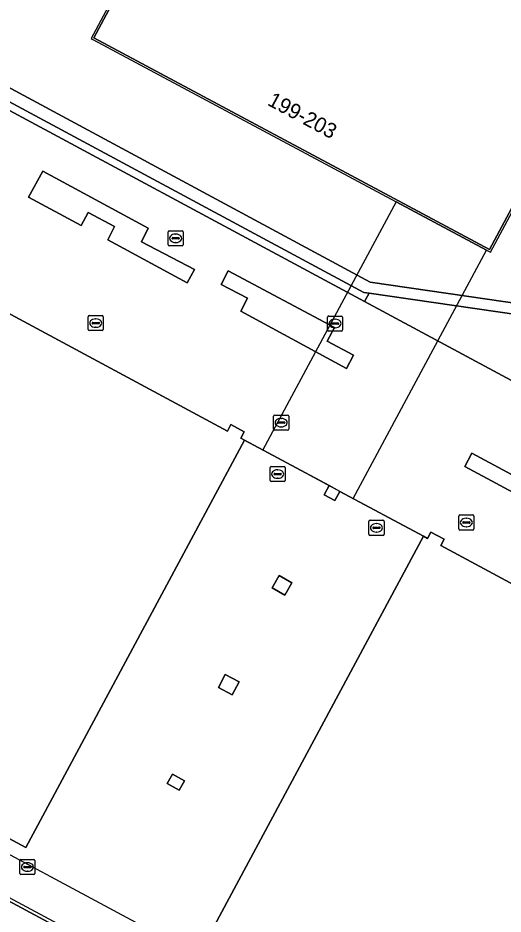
# Model space of a CAD drawing. Extents: x 159489 to 160304, y 383825 to 384531.
# Drawn here: x 159703.5 to 159735.7, y 384277.9 to 384337.5 of the extents above; entities that cross this region are included whole.
import ezdxf

# ---------------------------------------------------------------- set-up
doc = ezdxf.new("R2010")
doc.units = 0
for name, color, linetype in [('IMGEO_Dek', 7, 'Continuous'), ('IMGEO_Groenvoorziening', 7, 'Continuous'), ('IMGEO_Kolk', 7, 'Continuous'), ('IMGEO_Lijnafwatering', 7, 'Continuous'), ('IMGEO_Pand', 7, 'Continuous'), ('IMGEO_Pand_nummerreeks', 7, 'Continuous'), ('IMGEO_Pand_overbouw', 7, 'Continuous'), ('IMGEO_Rioolput', 7, 'Continuous'), ('IMGEO_Terreindeel_open', 7, 'Continuous'), ('IMGEO_Voetpad_gesloten', 7, 'Continuous'), ('IMGEO_Voetpad_open', 7, 'Continuous')]:
    doc.layers.add(name, color=color, linetype=linetype)

msp = doc.modelspace()

# ---------------------------------------------------------------- linework, layer by layer
at = {"layer": 'IMGEO_Dek'}
msp.add_lwpolyline([(159734.596, 384322.101), (159728.589, 384325.319), (159719.719, 384308.817), (159725.721, 384305.59)], close=True, dxfattribs=at)
at = {"layer": 'IMGEO_Groenvoorziening'}
for points in [[(159705.101, 384327.367), (159704.159, 384325.622), (159707.658, 384323.74), (159708.13, 384324.61), (159709.88, 384323.672), (159709.423, 384322.784), (159714.71, 384319.933), (159715.178, 384320.807), (159711.668, 384322.666), (159712.108, 384323.561)], [(159724.481, 384316.952), (159717.417, 384320.724), (159716.952, 384319.819), (159718.713, 384318.921), (159718.256, 384318.05), (159725.298, 384314.239), (159725.754, 384315.114), (159724.004, 384316.059)], [(159733.627, 384308.609), (159733.153, 384307.722), (159741.96, 384302.978), (159742.427, 384303.848)]]:
    msp.add_lwpolyline(points, close=True, dxfattribs=at)
at = {"layer": 'IMGEO_Kolk'}
for p, q in [((159713.436, 384322.465), (159713.436, 384323.317)), ((159713.511, 384323.391), (159714.363, 384323.391)), ((159713.738, 384322.934), (159714.136, 384322.934)), ((159713.924, 384323.171), (159713.949, 384323.171)), ((159714.437, 384323.317), (159714.437, 384322.465)), ((159714.363, 384322.391), (159713.511, 384322.391)), ((159713.695, 384322.885), (159713.695, 384322.897)), ((159714.133, 384322.848), (159713.735, 384322.848)), ((159713.947, 384322.611), (159713.922, 384322.611)), ((159714.179, 384322.897), (159714.179, 384322.885)), ((159708.125, 384316.825), (159708.125, 384317.677)), ((159708.2, 384317.751), (159709.052, 384317.751)), ((159709.126, 384317.677), (159709.126, 384316.825)), ((159724.028, 384316.798), (159724.028, 384317.65)), ((159724.103, 384317.724), (159724.955, 384317.724)), ((159725.029, 384317.65), (159725.029, 384316.798)), ((159708.384, 384317.245), (159708.384, 384317.257)), ((159708.822, 384317.208), (159708.424, 384317.208)), ((159708.427, 384317.294), (159708.825, 384317.294)), ((159708.636, 384316.971), (159708.611, 384316.971)), ((159708.613, 384317.531), (159708.638, 384317.531)), ((159708.868, 384317.257), (159708.868, 384317.245)), ((159724.287, 384317.218), (159724.287, 384317.23)), ((159724.725, 384317.181), (159724.327, 384317.181)), ((159724.33, 384317.267), (159724.728, 384317.267)), ((159724.516, 384317.504), (159724.541, 384317.504)), ((159724.771, 384317.23), (159724.771, 384317.218)), ((159709.052, 384316.751), (159708.2, 384316.751)), ((159724.955, 384316.724), (159724.103, 384316.724)), ((159724.539, 384316.944), (159724.514, 384316.944)), ((159720.445, 384310.206), (159720.445, 384311.058)), ((159720.52, 384311.132), (159721.372, 384311.132)), ((159721.446, 384311.058), (159721.446, 384310.206)), ((159720.704, 384310.626), (159720.704, 384310.638)), ((159721.142, 384310.589), (159720.744, 384310.589)), ((159720.747, 384310.675), (159721.145, 384310.675)), ((159720.933, 384310.912), (159720.958, 384310.912)), ((159721.188, 384310.638), (159721.188, 384310.626)), ((159721.372, 384310.132), (159720.52, 384310.132)), ((159720.956, 384310.352), (159720.931, 384310.352)), ((159720.214, 384306.786), (159720.214, 384307.638)), ((159720.289, 384307.712), (159721.141, 384307.712)), ((159720.702, 384307.492), (159720.727, 384307.492)), ((159721.215, 384307.638), (159721.215, 384306.786)), ((159720.473, 384307.206), (159720.473, 384307.218)), ((159720.911, 384307.169), (159720.513, 384307.169)), ((159720.516, 384307.255), (159720.914, 384307.255)), ((159720.725, 384306.932), (159720.7, 384306.932)), ((159720.957, 384307.218), (159720.957, 384307.206)), ((159721.141, 384306.712), (159720.289, 384306.712)), ((159732.827, 384304.491), (159733.679, 384304.491)), ((159726.779, 384303.211), (159726.779, 384304.063)), ((159726.854, 384304.137), (159727.706, 384304.137)), ((159727.267, 384303.917), (159727.292, 384303.917)), ((159727.78, 384304.063), (159727.78, 384303.211)), ((159732.752, 384303.565), (159732.752, 384304.417)), ((159733.011, 384303.985), (159733.011, 384303.997)), ((159733.449, 384303.948), (159733.051, 384303.948)), ((159733.054, 384304.034), (159733.452, 384304.034)), ((159733.24, 384304.271), (159733.265, 384304.271)), ((159733.495, 384303.997), (159733.495, 384303.985)), ((159733.753, 384304.417), (159733.753, 384303.565)), ((159727.038, 384303.631), (159727.038, 384303.643)), ((159727.476, 384303.594), (159727.078, 384303.594)), ((159727.081, 384303.68), (159727.479, 384303.68)), ((159727.29, 384303.357), (159727.265, 384303.357)), ((159727.522, 384303.643), (159727.522, 384303.631)), ((159733.679, 384303.491), (159732.827, 384303.491)), ((159733.263, 384303.711), (159733.238, 384303.711)), ((159727.706, 384303.137), (159726.854, 384303.137))]:
    msp.add_line(p, q, dxfattribs=at)
for points in [[(159713.436, 384322.465), (159713.436, 384323.317)], [(159713.511, 384323.391), (159714.363, 384323.391)], [(159714.437, 384323.317), (159714.437, 384322.465)], [(159714.363, 384322.391), (159713.511, 384322.391)], [(159708.125, 384316.825), (159708.125, 384317.677)], [(159708.2, 384317.751), (159709.052, 384317.751)], [(159709.126, 384317.677), (159709.126, 384316.825)], [(159724.028, 384316.798), (159724.028, 384317.65)], [(159724.103, 384317.724), (159724.955, 384317.724)], [(159725.029, 384317.65), (159725.029, 384316.798)], [(159709.052, 384316.751), (159708.2, 384316.751)], [(159724.955, 384316.724), (159724.103, 384316.724)], [(159720.445, 384310.206), (159720.445, 384311.058)], [(159720.52, 384311.132), (159721.372, 384311.132)], [(159721.446, 384311.058), (159721.446, 384310.206)], [(159721.372, 384310.132), (159720.52, 384310.132)], [(159720.214, 384306.786), (159720.214, 384307.638)], [(159720.289, 384307.712), (159721.141, 384307.712)], [(159721.215, 384307.638), (159721.215, 384306.786)], [(159721.141, 384306.712), (159720.289, 384306.712)], [(159732.827, 384304.491), (159733.679, 384304.491)], [(159726.779, 384303.211), (159726.779, 384304.063)], [(159726.854, 384304.137), (159727.706, 384304.137)], [(159727.78, 384304.063), (159727.78, 384303.211)], [(159732.752, 384303.565), (159732.752, 384304.417)], [(159733.753, 384304.417), (159733.753, 384303.565)], [(159733.679, 384303.491), (159732.827, 384303.491)], [(159727.706, 384303.137), (159726.854, 384303.137)]]:
    msp.add_lwpolyline(points, dxfattribs=at)
for centre, radius, start, end in [((159713.513, 384323.315), 0.0765, 91.55205, 178.44795), ((159713.513, 384323.315), 0.0765, 91.55205, 178.44795), ((159713.735, 384322.894), 0.0403, 85.87752, 175.75265), ((159714.14, 384322.896), 0.0386, 1.73085, 96.63898), ((159714.361, 384323.315), 0.0765, 1.55205, 88.44795), ((159714.361, 384323.315), 0.0765, 1.55205, 88.44795), ((159713.513, 384322.467), 0.0765, 181.55205, 268.44795), ((159713.513, 384322.467), 0.0765, 181.55205, 268.44795), ((159713.732, 384322.884), 0.0366, 178.93798, 274.71019), ((159714.136, 384322.891), 0.043, 264.86636, 352.45326), ((159714.361, 384322.467), 0.0765, 271.55205, 358.44795), ((159714.361, 384322.467), 0.0765, 271.55205, 358.44795), ((159708.202, 384317.675), 0.0765, 91.55205, 178.44795), ((159708.202, 384317.675), 0.0765, 91.55205, 178.44795), ((159709.05, 384317.675), 0.0765, 1.55205, 88.44795), ((159709.05, 384317.675), 0.0765, 1.55205, 88.44795), ((159724.105, 384317.648), 0.0765, 91.55205, 178.44795), ((159724.105, 384317.648), 0.0765, 91.55205, 178.44795), ((159724.953, 384317.648), 0.0765, 1.55205, 88.44795), ((159724.953, 384317.648), 0.0765, 1.55205, 88.44795), ((159708.424, 384317.254), 0.0403, 85.87752, 175.75265), ((159708.421, 384317.244), 0.0366, 178.93798, 274.71019), ((159708.825, 384317.251), 0.043, 264.86636, 352.45326), ((159708.829, 384317.256), 0.0386, 1.73085, 96.63898), ((159724.327, 384317.227), 0.0403, 85.87752, 175.75265), ((159724.324, 384317.217), 0.0366, 178.93798, 274.71019), ((159724.728, 384317.224), 0.043, 264.86636, 352.45326), ((159724.732, 384317.229), 0.0386, 1.73085, 96.63898), ((159708.202, 384316.827), 0.0765, 181.55205, 268.44795), ((159708.202, 384316.827), 0.0765, 181.55205, 268.44795), ((159709.05, 384316.827), 0.0765, 271.55205, 358.44795), ((159709.05, 384316.827), 0.0765, 271.55205, 358.44795), ((159724.105, 384316.8), 0.0765, 181.55205, 268.44795), ((159724.105, 384316.8), 0.0765, 181.55205, 268.44795), ((159724.953, 384316.8), 0.0765, 271.55205, 358.44795), ((159724.953, 384316.8), 0.0765, 271.55205, 358.44795), ((159720.522, 384311.056), 0.0765, 91.55205, 178.44795), ((159720.522, 384311.056), 0.0765, 91.55205, 178.44795), ((159721.37, 384311.056), 0.0765, 1.55205, 88.44795), ((159721.37, 384311.056), 0.0765, 1.55205, 88.44795), ((159720.744, 384310.635), 0.0403, 85.87752, 175.75265), ((159720.741, 384310.625), 0.0366, 178.93798, 274.71019), ((159721.145, 384310.632), 0.043, 264.86636, 352.45326), ((159721.149, 384310.637), 0.0386, 1.73085, 96.63898), ((159720.522, 384310.208), 0.0765, 181.55205, 268.44795), ((159720.522, 384310.208), 0.0765, 181.55205, 268.44795), ((159721.37, 384310.208), 0.0765, 271.55205, 358.44795), ((159721.37, 384310.208), 0.0765, 271.55205, 358.44795), ((159720.291, 384307.636), 0.0765, 91.55205, 178.44795), ((159720.291, 384307.636), 0.0765, 91.55205, 178.44795), ((159721.139, 384307.636), 0.0765, 1.55205, 88.44795), ((159721.139, 384307.636), 0.0765, 1.55205, 88.44795), ((159720.513, 384307.215), 0.0403, 85.87752, 175.75265), ((159720.51, 384307.205), 0.0366, 178.93798, 274.71019), ((159720.914, 384307.212), 0.043, 264.86636, 352.45326), ((159720.918, 384307.217), 0.0386, 1.73085, 96.63898), ((159720.291, 384306.788), 0.0765, 181.55205, 268.44795), ((159720.291, 384306.788), 0.0765, 181.55205, 268.44795), ((159721.139, 384306.788), 0.0765, 271.55205, 358.44795), ((159721.139, 384306.788), 0.0765, 271.55205, 358.44795), ((159732.829, 384304.415), 0.0765, 91.55205, 178.44795), ((159732.829, 384304.415), 0.0765, 91.55205, 178.44795), ((159733.677, 384304.415), 0.0765, 1.55205, 88.44795), ((159733.677, 384304.415), 0.0765, 1.55205, 88.44795), ((159726.856, 384304.061), 0.0765, 91.55205, 178.44795), ((159726.856, 384304.061), 0.0765, 91.55205, 178.44795), ((159727.704, 384304.061), 0.0765, 1.55205, 88.44795), ((159727.704, 384304.061), 0.0765, 1.55205, 88.44795), ((159733.051, 384303.994), 0.0403, 85.87752, 175.75265), ((159733.048, 384303.984), 0.0366, 178.93798, 274.71019), ((159733.452, 384303.991), 0.043, 264.86636, 352.45326), ((159733.456, 384303.996), 0.0386, 1.73085, 96.63898), ((159727.078, 384303.64), 0.0403, 85.87752, 175.75265), ((159727.075, 384303.63), 0.0366, 178.93798, 274.71019), ((159727.479, 384303.637), 0.043, 264.86636, 352.45326), ((159727.483, 384303.642), 0.0386, 1.73085, 96.63898), ((159732.829, 384303.567), 0.0765, 181.55205, 268.44795), ((159732.829, 384303.567), 0.0765, 181.55205, 268.44795), ((159733.677, 384303.567), 0.0765, 271.55205, 358.44795), ((159733.677, 384303.567), 0.0765, 271.55205, 358.44795), ((159726.856, 384303.213), 0.0765, 181.55205, 268.44795), ((159726.856, 384303.213), 0.0765, 181.55205, 268.44795), ((159727.704, 384303.213), 0.0765, 271.55205, 358.44795), ((159727.704, 384303.213), 0.0765, 271.55205, 358.44795)]:
    msp.add_arc(centre, radius, start, end, dxfattribs=at)
for centre, major_axis, ratio, start_param, end_param in [((159713.923, 384322.891), (-0.387, 0.002), 0.722429, 4.712389, 7.853982), ((159713.948, 384322.891), (-0.39, 0.002), 0.717154, 1.570796, 4.712389), ((159708.612, 384317.251), (-0.387, 0.002), 0.722429, 4.712389, 7.853982), ((159708.637, 384317.251), (-0.39, 0.002), 0.717154, 1.570796, 4.712389), ((159724.515, 384317.224), (-0.387, 0.002), 0.722429, 4.712389, 7.853982), ((159724.54, 384317.224), (-0.39, 0.002), 0.717154, 1.570796, 4.712389), ((159720.932, 384310.632), (-0.387, 0.002), 0.722429, 4.712389, 7.853982), ((159720.957, 384310.632), (-0.39, 0.002), 0.717154, 1.570796, 4.712389), ((159720.701, 384307.212), (-0.387, 0.002), 0.722429, 4.712389, 7.853982), ((159720.726, 384307.212), (-0.39, 0.002), 0.717154, 1.570796, 4.712389), ((159727.266, 384303.637), (-0.387, 0.002), 0.722429, 4.712389, 7.853982), ((159727.291, 384303.637), (-0.39, 0.002), 0.717154, 1.570796, 4.712389), ((159733.239, 384303.991), (-0.387, 0.002), 0.722429, 4.712389, 7.853982), ((159733.264, 384303.991), (-0.39, 0.002), 0.717154, 1.570796, 4.712389)]:
    msp.add_ellipse(centre, major_axis=major_axis, ratio=ratio, start_param=start_param, end_param=end_param, dxfattribs=at)
at = {"layer": 'IMGEO_Lijnafwatering'}
msp.add_lwpolyline([(159711.214, 384274.544), (159694.446, 384283.552)], dxfattribs=at)
at = {"layer": 'IMGEO_Pand'}
for points in [[(159744.495, 384340.27), (159745.463, 384342.08), (159719.159, 384356.157), (159718.221, 384354.406), (159717.843, 384353.7), (159708.49, 384336.235), (159734.794, 384322.143), (159744.117, 384339.565)], [(159718.52, 384309.461), (159718.256, 384309.603), (159718.485, 384310.029), (159717.604, 384310.502), (159717.376, 384310.076), (159693.74, 384322.781), (159693.668, 384322.82), (159692.216, 384320.108), (159684.806, 384306.264), (159683.295, 384303.441), (159678.693, 384294.844), (159693.021, 384287.138), (159693.055, 384287.196), (159693.529, 384288.01), (159703.988, 384282.369)], [(159747.439, 384293.915), (159731.551, 384302.457), (159731.779, 384302.882), (159730.898, 384303.355), (159730.67, 384302.93), (159730.406, 384303.072), (159715.868, 384275.99), (159766.025, 384249.054), (159765.572, 384248.208), (159765.546, 384248.161), (159779.824, 384240.489), (159781.812, 384244.448), (159783.972, 384248.491), (159794.191, 384267.623), (159794.673, 384268.525)], [(159721.661, 384299.975), (159720.815, 384300.466), (159720.343, 384299.654), (159721.19, 384299.162)], [(159718.149, 384293.384), (159717.236, 384293.874), (159716.775, 384293.016), (159717.688, 384292.525)], [(159714.521, 384286.819), (159713.736, 384287.261), (159713.378, 384286.626), (159714.163, 384286.183)]]:
    msp.add_lwpolyline(points, close=True, dxfattribs=at)
at = {"layer": 'IMGEO_Pand_overbouw'}
for points in [[(159772.845, 384392.873), (159746.364, 384407.132), (159719.057, 384356.211), (159708.316, 384336.181), (159708.428, 384336.121), (159728.589, 384325.319), (159734.596, 384322.101), (159734.859, 384321.96), (159745.598, 384342.008)], [(159745.463, 384342.08), (159744.495, 384340.27), (159744.117, 384339.565), (159734.794, 384322.143), (159708.49, 384336.235), (159717.843, 384353.7), (159718.221, 384354.406), (159719.159, 384356.157)], [(159718.52, 384309.461), (159703.988, 384282.369), (159693.529, 384288.01), (159693.055, 384287.196), (159765.572, 384248.208), (159766.025, 384249.054), (159715.868, 384275.99), (159730.406, 384303.072), (159724.846, 384306.056), (159724.134, 384306.443)]]:
    msp.add_lwpolyline(points, close=True, dxfattribs=at)
at = {"layer": 'IMGEO_Rioolput'}
for p, q in [((159703.583, 384280.651), (159703.583, 384281.503)), ((159703.658, 384281.577), (159704.51, 384281.577)), ((159704.071, 384281.357), (159704.096, 384281.357)), ((159704.584, 384281.503), (159704.584, 384280.651)), ((159703.842, 384281.071), (159703.842, 384281.083)), ((159704.28, 384281.034), (159703.882, 384281.034)), ((159703.885, 384281.12), (159704.283, 384281.12)), ((159704.094, 384280.797), (159704.069, 384280.797)), ((159704.326, 384281.083), (159704.326, 384281.071)), ((159704.51, 384280.577), (159703.658, 384280.577))]:
    msp.add_line(p, q, dxfattribs=at)
for points in [[(159703.583, 384280.651), (159703.583, 384281.503)], [(159703.658, 384281.577), (159704.51, 384281.577)], [(159704.584, 384281.503), (159704.584, 384280.651)], [(159704.51, 384280.577), (159703.658, 384280.577)]]:
    msp.add_lwpolyline(points, dxfattribs=at)
for centre, radius, start, end in [((159703.66, 384281.501), 0.0765, 91.55205, 178.44795), ((159703.66, 384281.501), 0.0765, 91.55205, 178.44795), ((159704.508, 384281.501), 0.0765, 1.55205, 88.44795), ((159704.508, 384281.501), 0.0765, 1.55205, 88.44795), ((159703.66, 384280.653), 0.0765, 181.55205, 268.44795), ((159703.66, 384280.653), 0.0765, 181.55205, 268.44795), ((159703.882, 384281.08), 0.0403, 85.87752, 175.75265), ((159703.879, 384281.07), 0.0366, 178.93798, 274.71019), ((159704.283, 384281.077), 0.043, 264.86636, 352.45326), ((159704.287, 384281.082), 0.0386, 1.73085, 96.63898), ((159704.508, 384280.653), 0.0765, 271.55205, 358.44795), ((159704.508, 384280.653), 0.0765, 271.55205, 358.44795)]:
    msp.add_arc(centre, radius, start, end, dxfattribs=at)
for centre, major_axis, ratio, start_param, end_param in [((159704.07, 384281.077), (-0.387, 0.002), 0.722429, 4.712389, 7.853982), ((159704.095, 384281.077), (-0.39, 0.002), 0.717154, 1.570796, 4.712389)]:
    msp.add_ellipse(centre, major_axis=major_axis, ratio=ratio, start_param=start_param, end_param=end_param, dxfattribs=at)
at = {"layer": 'IMGEO_Terreindeel_open'}
msp.add_lwpolyline([(159797.007, 384309.896), (159741.046, 384317.91), (159726.866, 384319.977), (159700.707, 384334.064), (159712.762, 384356.443), (159717.843, 384353.7), (159718.221, 384354.406), (159712.442, 384357.532), (159699.61, 384333.72), (159726.44, 384319.286), (159726.801, 384319.234), (159741.002, 384317.183), (159741.576, 384317.086), (159796.909, 384309.117), (159800.043, 384308.652), (159800.185, 384309.411), (159801.736, 384308.601), (159802.101, 384309.308), (159781.459, 384320.418), (159744.495, 384340.27), (159744.117, 384339.565), (159781.262, 384319.609), (159800.092, 384309.462)], close=True, dxfattribs=at)
at = {"layer": 'IMGEO_Voetpad_gesloten'}
for points in [[(159744.117, 384339.565), (159734.794, 384322.143), (159708.49, 384336.235), (159717.843, 384353.7), (159712.762, 384356.443), (159700.707, 384334.064), (159726.866, 384319.977), (159741.046, 384317.91), (159797.007, 384309.896), (159800.092, 384309.462), (159781.262, 384319.609)], [(159734.596, 384322.101), (159728.589, 384325.319), (159719.719, 384308.817), (159725.721, 384305.59)]]:
    msp.add_lwpolyline(points, close=True, dxfattribs=at)
at = {"layer": 'IMGEO_Voetpad_open'}
for points in [[(159712.442, 384357.532), (159712.638, 384357.799), (159712.207, 384358.023), (159699.16, 384333.403), (159699.381, 384333.281), (159726.485, 384318.691), (159726.801, 384319.234), (159726.44, 384319.286), (159699.61, 384333.72)], [(159705.101, 384327.367), (159712.108, 384323.561), (159711.668, 384322.666), (159715.178, 384320.807), (159714.71, 384319.933), (159709.423, 384322.784), (159709.88, 384323.672), (159708.13, 384324.61), (159707.658, 384323.74), (159704.159, 384325.622)], [(159724.481, 384316.952), (159724.004, 384316.059), (159725.754, 384315.114), (159725.298, 384314.239), (159718.256, 384318.05), (159718.713, 384318.921), (159716.952, 384319.819), (159717.417, 384320.724)], [(159726.801, 384319.234), (159726.485, 384318.691), (159736.839, 384313.125), (159737.034, 384313.652), (159737.45, 384314.29), (159738.511, 384313.717), (159738.631, 384314.476), (159741.156, 384314.134), (159741.576, 384317.086), (159741.002, 384317.183)], [(159733.627, 384308.609), (159742.427, 384303.848), (159741.96, 384302.978), (159733.153, 384307.722)], [(159721.19, 384299.162), (159720.343, 384299.654), (159720.815, 384300.466), (159721.661, 384299.975)], [(159717.688, 384292.525), (159716.775, 384293.016), (159717.236, 384293.874), (159718.149, 384293.384)], [(159778.522, 384238.137), (159677.536, 384292.428), (159674.737, 384287.233), (159775.75, 384232.935)], [(159778.522, 384238.137), (159775.75, 384232.935), (159674.737, 384287.233), (159677.536, 384292.428)], [(159714.163, 384286.183), (159713.378, 384286.626), (159713.736, 384287.261), (159714.521, 384286.819)]]:
    msp.add_lwpolyline(points, close=True, dxfattribs=at)
for points in [[(159800.352, 384278.938), (159736.839, 384313.125), (159726.485, 384318.691), (159699.381, 384333.281)], [(159693.74, 384322.781), (159717.376, 384310.076), (159717.604, 384310.502), (159718.485, 384310.029), (159718.256, 384309.603), (159718.52, 384309.461), (159724.134, 384306.443), (159723.803, 384305.826), (159724.517, 384305.443), (159724.846, 384306.056), (159730.406, 384303.072), (159730.67, 384302.93), (159730.898, 384303.355), (159731.779, 384302.882), (159731.551, 384302.457), (159747.439, 384293.915), (159794.673, 384268.525)], [(159715.868, 384275.99), (159730.406, 384303.072), (159724.846, 384306.056), (159724.517, 384305.443), (159723.803, 384305.826), (159724.134, 384306.443), (159718.52, 384309.461), (159703.988, 384282.369), (159693.529, 384288.01), (159693.055, 384287.196), (159693.021, 384287.138), (159678.693, 384294.844), (159676.707, 384295.949), (159673.838, 384290.575)]]:
    msp.add_lwpolyline(points, dxfattribs=at)

# ---------------------------------------------------------------- texts
at = {"layer": 'IMGEO_Pand_nummerreeks'}
msp.add_text('199-203', height=1, rotation=331.82194, dxfattribs=at).set_placement((159719.969, 384331.787))

doc.saveas('drawing.dxf')
